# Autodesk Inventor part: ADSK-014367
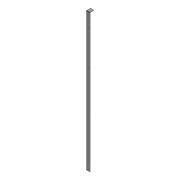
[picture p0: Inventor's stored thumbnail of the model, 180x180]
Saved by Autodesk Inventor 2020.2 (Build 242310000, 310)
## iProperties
Created: 2019-10
Part Number: ADSK-014367
Material: 1.0312 DC05
Document SubType Name: Blech
Designer: lutzd
Mass: 558.443 g
Surface Area: 3843.93 cm^2
Volume: 558.443 cm^3
Density: 1 g/cm^3
Sheet Metal Rule: Stahlblech 1.0312 - DC05 -   3.0 mm
Appearance: Stahl
Flat Pattern Width: 186.979 cm
Flat Pattern Length: 10.0786 cm
Flat Pattern Area: 1884.48 cm^2
Sheet Metal Width: 1869,786 mm
Sheet Metal Length: 100,786 mm
Sheet Metal Area: 188447,937 mm^2
VLDS_Profile: Default Part
VLDS_TimeStamp: 2016-07-29
VLDS_FailCnt: 0
VLDS_AcceptCnt: 0
Dimensions: 53,1x1825,1x53,1 mm
Semi finished: Stahlblech 1.0312 - DC05 -   3.0 mm
Mass: 0,558 kg
DocNumber: ADSK-014367
Folder: 01 - Themengebiete\Simplification\01 - Packaging machine\
Original: C:\AB_Vault\CAD\01 - Themengebiete\Simplification\01 - Packaging machine\Parts\ADSK-014366.ipt
VDS_Category: 3D Komponenten
VDS_NumSchm: Autodesk
G_L: 1869,8x100,8 mm
Thickness: 3,000 mm
VLT_Material: 1.0312 DC05
Title: rail
Author: lutzd
Revision Number: -
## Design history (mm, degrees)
node "Konturlasche1"
  sketch "Skizze1"
    geometry: L1 (0, 0)-(0, 50); L2 (0, 0)-(50, 0)
    constraints: 4 end point, 1 horizontal, 1 vertical
    dimensions: "d0" = 50 distance of L1.start L2.end; "d1" = 50 distance of L1.start L1.end
sketch "Skizze2"
  geometry: L1 (10.6, 1050)-(-63.6, 1050) reference; L2 (0, 2100)-(0, 0) reference; L3 (-25, 255)-(-25, 1845); 5 further points
  constraints: 4 point on line, 2 end point, 1 midpoint, 1 vertical
  dimensions: "d22" = 1590 distance of L3.start L3.end; "d23" = 530 distance of L3.end point (-25, 1315) (= 0.333333 x d22); "d24" = 530 distance of L3.start point (-25, 785) (= 0.333333 x d22); "d25" = 25 distance between parallel lines of L2 L3; "d39" = 80 distance of L3.start point (-25, 335)
hole "Bohrung1" sketch "Skizze2" at (-25, 785), (-25, 1315), (-25, 1845), (-25, 335) diameter "d15" = 6.6; stored, may be unused: countersink angle "d19" = 90 deg, drill point angle "d21" = 118 deg; dims "d16" = 16, "d17" = 12.6, "d18" = 2, "d20" = 3 (= Stärke)
workplane "Arbeitsebene1"
feature "Trennen1"
node "Lasche3"
feature "Ecke6" dims "d2" = 3 (= Stärke), "d66" = 12 (= GrößeEckenfreistellung), "d67" = 3 (= Übergangsradius), "d68" = 3 (= Abstandsgröße), "d69" = 0, "d70" = 10
node "Lasche2"
feature "Ecke4" dims "d2" = 3 (= Stärke), "d50" = 12 (= GrößeEckenfreistellung), "d51" = 3 (= Übergangsradius), "d52" = 3 (= Abstandsgröße), "d53" = 0, "d54" = 10
node "Volumenkörper1"
feature "Grobblech1" dims "d2" = 3 (= Stärke), "d3" = 3 (= BreiteBiegungsfreistellung), "d4" = 1.5 (= TiefeBiegungsfreistellung), "d5" = 6 (= MinimalRest), "d6" = 3 (= Übergangsradius), "d7" = 2100, "d8" = 3 (= Biegeradius), "d9" = 3, "d10" = 12 (= GrößeEckenfreistellung), "d11" = 3 (= Abstandsgröße), "d12" = 3 (= JacobiRadiusGröße), "AbstandVerbindung" = 0.01
feature "Biegung1" dims "d2" = 3 (= Stärke), "d3" = 3 (= BreiteBiegungsfreistellung), "d4" = 1.5 (= TiefeBiegungsfreistellung), "d5" = 6 (= MinimalRest), "d6" = 3 (= Übergangsradius), "d8" = 3 (= Biegeradius), "d9" = 3, "AbstandVerbindung" = 0.01
feature "Ecke1" dims "d9" = 3, "d10" = 12 (= GrößeEckenfreistellung), "d11" = 3 (= Abstandsgröße), "d12" = 3 (= JacobiRadiusGröße)
sketch "Skizze5"
  geometry: L1 through (0, 23.5) direction (1.18e-17, -1); L2 through (25, 0) direction (1, -8.19e-34); L3 (50, 0)-(50, 47); L4 (50, 47)-(0, 47)
  constraints: 6 end point, 1 horizontal, 1 perpendicular, 1 vertical
feature "Grobblech3" dims "d2" = 3 (= Stärke), "d40" = 3 (= BreiteBiegungsfreistellung), "d41" = 1.5 (= TiefeBiegungsfreistellung), "d42" = 6 (= MinimalRest), "d43" = 3 (= Übergangsradius), "d44" = 50, "d45" = 90 deg, "d46" = 3 (= Biegeradius), "d47" = 12 (= GrößeEckenfreistellung), "d48" = 3 (= Abstandsgröße), "d49" = 3 (= JacobiRadiusGröße), "AbstandVerbindung" = 0.01
feature "Biegung3" dims "d2" = 3 (= Stärke), "d40" = 3 (= BreiteBiegungsfreistellung), "d41" = 1.5 (= TiefeBiegungsfreistellung), "d42" = 6 (= MinimalRest), "d43" = 3 (= Übergangsradius), "d44" = 50, "d45" = 90 deg, "d46" = 3 (= Biegeradius), "AbstandVerbindung" = 0.01
feature "Ecke3" dims "d44" = 50, "d45" = 90 deg, "d47" = 12 (= GrößeEckenfreistellung), "d48" = 3 (= Abstandsgröße), "d49" = 3 (= JacobiRadiusGröße)
sketch "Skizze6"
  geometry: L1 through (0, 23.5) direction (0, -1); L2 through (25, 0) direction (1, 1.11e-17); L3 (50, 0)-(50, 47); L4 (50, 47)-(0, 47)
  constraints: 6 end point, 1 horizontal, 1 perpendicular, 1 vertical
feature "Grobblech4" dims "d2" = 3 (= Stärke), "d56" = 3 (= BreiteBiegungsfreistellung), "d57" = 1.5 (= TiefeBiegungsfreistellung), "d58" = 6 (= MinimalRest), "d59" = 3 (= Übergangsradius), "d60" = 50, "d61" = 90 deg, "d62" = 3 (= Biegeradius), "d63" = 12 (= GrößeEckenfreistellung), "d64" = 3 (= Abstandsgröße), "d65" = 3 (= JacobiRadiusGröße), "AbstandVerbindung" = 0.01
feature "Biegung4" dims "d2" = 3 (= Stärke), "d56" = 3 (= BreiteBiegungsfreistellung), "d57" = 1.5 (= TiefeBiegungsfreistellung), "d58" = 6 (= MinimalRest), "d59" = 3 (= Übergangsradius), "d60" = 50, "d61" = 90 deg, "d62" = 3 (= Biegeradius), "AbstandVerbindung" = 0.01
feature "Ecke5" dims "d60" = 50, "d61" = 90 deg, "d63" = 12 (= GrößeEckenfreistellung), "d64" = 3 (= Abstandsgröße), "d65" = 3 (= JacobiRadiusGröße)
feature "Definition1"
other parameters: "Stärke" = 3 (derived), "KFaktor" = 4.4, "Biegeradius" = 3 (= Stärke), "BreiteBiegungsfreistellung" = 3 (= Stärke), "TiefeBiegungsfreistellung" = 1.5 (= 0.5 x Stärke), "GrößeEckenfreistellung" = 12 (= 4 x Stärke), "MinimalRest" = 6 (= 2 x Stärke), "Übergangsradius" = 3 (= Biegeradius), "JacobiRadiusGröße" = 3 (= Biegeradius), "Abstandsgröße" = 3 (= Stärke), "d55" = -275, "Abstandsgröße" = 3, "Biegeradius" = 3, "BreiteBiegungsfreistellung" = 3, "GrößeEckenfreistellung" = 12, "JacobiRadiusGröße" = 3, "MinimalRest" = 6, "Stärke" = 3, "TiefeBiegungsfreistellung" = 1.5, "Übergangsradius" = 3
